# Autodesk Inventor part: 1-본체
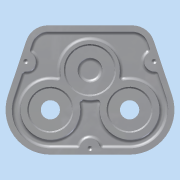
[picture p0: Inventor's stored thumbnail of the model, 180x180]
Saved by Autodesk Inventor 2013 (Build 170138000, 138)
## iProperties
Created: 2014-12
Part Number: 1-본체
Material: 알루미늄 6061
Document SubType Name: Modeling
Designer: WINDOWS7
Density: 2.71 g/cm^3
Mass: 605.676 g
Surface Area: 658.163 cm^2
Volume: 223.497 cm^3
Author: WINDOWS7
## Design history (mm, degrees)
sketch "스케치1"
  geometry: L1 (-31.82, -31.82)-(31.82, -31.82); L2 (-47, 36)-(47, 36); L3 (-31.82, -67.82)-(31.82, -67.82); L4 (-47, 36)-(-65.943, -20.348); L5 (47, 36)-(65.943, -20.348); A1 r 45 centre (0, 0) between (-31.82, -31.82) and (31.82, -31.82); A2 r 36 centre (-31.82, -31.82) between (-31.82, -67.82) and (-65.943, -20.348); A3 r 36 centre (31.82, -31.82) between (31.82, -67.82) and (65.943, -20.348); 2 further points
  constraints: 10 end point, 6 point on circle, 3 centre point, 2 horizontal, 2 tangent, 1 coincident, 1 equal length, 1 equal radius, 1 horizontal alignment, 1 midpoint, 1 parallel, 1 vertical alignment
  dimensions: "d0" = 90 diameter of A1; "d1" = 72 diameter of A2; "d2" = 90 deg dimension on point (0, 0) L1.end L1.start; "d3" = 94 distance of L2.start L2.end; "d4" = 36 distance of point (0, 0) point (0, 36)
extrude "돌출1" new body sketch "스케치1" distance "d5" = 44; taper "d6" = 0 deg
fillet "모깎기1" dims "d7" = 18
sketch "스케치2"
  geometry: L1 (34.061, 36)-(-34.061, 36) reference; L2 (-51.123, 23.736)-(-65.943, -20.348) reference; L3 (-31.82, -67.82)-(31.82, -67.82) reference; L4 (65.943, -20.348)-(51.123, 23.736) reference; L5 (-34.061, 31)-(34.061, 31); L6 (46.384, 22.143)-(61.204, -21.941); L7 (31.82, -62.82)-(-31.82, -62.82); L8 (-61.204, -21.941)-(-46.384, 22.143); A1 r 18 centre (34.061, 18) between (51.123, 23.736) and (34.061, 36) reference; A2 r 18 centre (-34.061, 18) between (-34.061, 36) and (-51.123, 23.736) reference; A3 r 36 centre (-31.82, -31.82) between (-65.943, -20.348) and (-31.82, -67.82) reference; A4 r 36 centre (31.82, -31.82) between (31.82, -67.82) and (65.943, -20.348) reference; A5 r 13 centre (34.061, 18) between (46.384, 22.143) and (34.061, 31); A6 r 31 centre (31.82, -31.82) between (31.82, -62.82) and (61.204, -21.941); A7 r 31 centre (-31.82, -31.82) between (-61.204, -21.941) and (-31.82, -62.82); A8 r 13 centre (-34.061, 18) between (-34.061, 31) and (-46.384, 22.143); A9 r 8 centre (51.474, 7) between (48.925, 14.583) and (54.023, -0.583); A10 r 8 centre (-51.474, 7) between (-54.023, -0.583) and (-48.925, 14.583); A11 r 8 centre (0, -62.82) between (8, -62.82) and (-8, -62.82); 1 further point
  constraints: 14 point on circle, 8 end point, 8 point on line, 7 centre point, 2 equal radius, 1 horizontal alignment, 1 midpoint, 7 other
  dimensions: "d8" = 5 distance between parallel lines of L5 L1; "d9" = 29 distance from line of A9.centre L1; "d10" = 16 diameter of A9
extrude "돌출2" cut sketch "스케치2" distance "d11" = 34; taper "d12" = 0 deg
fillet "모깎기2" dims "d13" = 3
sketch "스케치3"
  geometry: C1 r 24 at (-31.82, -31.82); C2 r 24 at (0, 0); C3 r 24 at (31.82, -31.82); A1 r 31 centre (-31.82, -31.82) between (-61.204, -21.941) and (-31.82, -62.82) reference; A2 r 31 centre (31.82, -31.82) between (31.82, -62.82) and (61.204, -21.941) reference; 1 further point
  constraints: 3 centre point, 3 coincident, 2 equal radius
  dimensions: "d14" = 48 diameter of C2
extrude "돌출3" join sketch "스케치3" distance "d16" = 11; taper "d17" = 0 deg
fillet "모깎기3" dims "d18" = 3
fillet "모깎기4" dims "d19" = 3
sketch "스케치4"
  geometry: C1 r 20 at (-31.82, -31.82); C2 r 20 at (31.82, -31.82); A1 r 33 centre (-31.82, -31.82) between (-63.1, -21.304) and (-31.82, -64.82) reference; A2 r 33 centre (31.82, -31.82) between (31.82, -64.82) and (63.1, -21.304) reference; 1 further point
  constraints: 2 centre point, 2 coincident, 1 equal radius
  dimensions: "d20" = 40 diameter of C1
extrude "돌출4" join sketch "스케치4" distance "d22" = 7; taper "d23" = -10 deg
fillet "모깎기5" dims "d24" = 3
sketch "스케치5"
  geometry: C1 r 17.5 at (-31.82, -31.82); C2 r 17.5 at (31.82, -31.82); A1 r 24 centre (-31.82, -31.82) between (-27.059, -8.297) and (-8.297, -27.059) reference; A2 r 24 centre (31.82, -31.82) between (8.297, -27.059) and (27.059, -8.297) reference
  constraints: 2 centre point, 2 coincident, 1 equal radius
  dimensions: "d25" = 35 diameter of C1
extrude "돌출5" cut sketch "스케치5" distance "d27" = 11; taper "d28" = 0 deg
sketch "스케치6"
  geometry: C1 r 20 at (0, 0); A1 r 24 centre (0, 0) between (23.523, -4.761) and (-23.523, -4.761) reference
  constraints: 1 centre point, 1 coincident
  dimensions: "d29" = 40 diameter of C1
extrude "돌출6" cut sketch "스케치6" distance "d30" = 12; taper "d31" = 0 deg
sketch "스케치7"
  geometry: C1 r 20 at (0, 0) reference; C2 r 10 at (0, 0)
  constraints: 1 centre point, 1 coincident
  dimensions: "d32" = 20 diameter of C2
extrude "돌출7" cut sketch "스케치7" distance "d33" = 3; taper "d34" = 0 deg
sketch "스케치8"
  geometry: C1 r 17.5 at (0, 0) reference; C2 r 7.75 at (0, 0); C3 r 17.5 at (63.64, 0) reference; C4 r 7.75 at (63.64, 0); 1 further point
  constraints: 2 centre point, 2 coincident, 1 equal radius
  dimensions: "d35" = 15.5 diameter of C2
extrude "돌출8" cut sketch "스케치8" distance "d36" = 10; taper "d37" = 0 deg
sketch "스케치9"
  geometry: C1 r 7.75 at (0, 0) reference; C2 r 15 at (0, 0); C3 r 17.5 at (63.64, 0) reference; C4 r 15 at (63.64, 0); 1 further point
  constraints: 2 centre point, 2 coincident, 1 equal radius
  dimensions: "d38" = 30 diameter of C2
extrude "돌출9" cut sketch "스케치9" distance "d39" = 7; taper "d40" = 0 deg
chamfer "모따기1" distance "d41" = 1; stored, may be unused: second distance "d42" = 2, angle "d43" = 45 deg
fillet "모깎기6" dims "d44" = 3, "d45" = 0.3, "d46" = 0.1
fillet "모깎기7" dims "d47" = 3
sketch "스케치10"
  geometry: A1 r 8 centre (51.474, 7) between (46.954, 13.6) and (51.859, -0.991) reference; A2 r 8 centre (0, -62.82) between (7.697, -60.638) and (-7.697, -60.638) reference; A3 r 8 centre (-51.474, 7) between (-51.859, -0.991) and (-46.954, 13.6) reference; 4 further points
  constraints: 3 coincident
hole "구멍1" sketch "스케치10" at (-51.474, 7), (51.474, 7), (0, -62.82) diameter "d48" = 4.134; stored, may be unused: countersink angle "d52" = 90 deg, drill point angle "d54" = 118 deg; dims "d49" = 20, "d50" = 4, "d51" = 2, "d53" = 23
sketch "스케치11"
  geometry: L1 (34.061, 36)-(-34.061, 36) reference; 2 further points
  constraints: 1 vertical alignment, 1 other
  dimensions: "d55" = 30 distance from line of point (0, 6) L1
feature "엠보싱1" sketch "스케치11" dims "d56" = 1, "d57" = 0
node "솔리드1"
node "투영된 루프1"
